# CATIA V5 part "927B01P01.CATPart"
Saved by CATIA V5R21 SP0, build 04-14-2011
Part number: 927B01P01
Bounding box of the stored display mesh (mm): x -17.1 to 17.1, y -76.2 to 76.2, z -4.4 to 4.4
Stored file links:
  C:\Users\ALI OZGUN\Desktop\alhan\927B01P01.CATPart
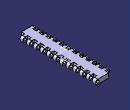
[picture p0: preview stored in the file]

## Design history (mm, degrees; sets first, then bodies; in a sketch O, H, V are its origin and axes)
Body1 (main body)
  Sketch1 on zx-plane, origin (0, 0, 0), H (-1, 0, 0), V (0, 0, 1)
    construction line L1 (-12.7, 0) -> (12.7, 0)
    point P1 (-12.7, 0)
    line L2 (-12.7, 4.4) -> (12.7, 4.4)
    line L3 (12.7, -4.4) -> (-12.7, -4.4)
    arc A1 centre (12.7, 0) radius 4.4 from (12.7, 4.4) to (12.7, -4.4) cw
    arc A2 centre (-12.7, 0) radius 4.4 from (-12.7, -4.4) to (-12.7, 4.4) cw
    distance L1 L2 = 4.4
    length L1 = 25.4
    distance P1 V = 12.7
    coincidence: P1 H
    horizontal: L1 H
    tangency: A1 L2, A2 L2, A1 L3, A2 L3
  Pad1: profile Sketch1, direction (0, 1, 0), length 76.2, mirrored extent
  Sketch2 on face of Pad1 from Sketch1.L2, origin (0, 0, 4.4), H (1, 0, 0), V (0, 1, 0)
    line L1 (-22.3127, -63.5) -> (-9.75, -63.5)
    line L2 (-9.75, -63.5) -> (-9.75, -70.6)
    line L3 (-9.75, -70.6) -> (-22.3127, -70.6)
    line L4 (-22.3127, -70.6) -> (-22.3127, -63.5)
    line L5 (24.6678, -76.95) -> (9.75, -76.95)
    line L6 (9.75, -76.95) -> (9.75, -69.85)
    line L7 (9.75, -69.85) -> (24.6678, -69.85)
    line L8 (24.6678, -69.85) -> (24.6678, -76.95)
    reference projected line E1 (-12.7, -76.2) -> (12.7, -76.2) from edge [start face of Pad1 | face of Pad1 from Sketch1.L2]
    reference projected line E2 (-12.7, -76.2) -> (12.7, -76.2) from edge [start face of Pad1 | face of Pad1 from Sketch1.L2]
    distance L3 E1 = 5.6
    length L4 = 7.1
    distance L7 L5 = 7.1
    distance L5 E2 = 0.75
    distance L2 L6 = 19.5
    distance L2 V = 9.75
    horizontal: L1 H, L3 H, L5 H, L7 H
    vertical: L2 V, L4 V, L6 V, L8 V
  Pocket1: profile Sketch2, direction (0, 0, -1), length 76.2
  RectPattern1: of Pocket1, direction 1 instances 12, spacing 12.7, along axis of face of Pad1 from Sketch1.A2
  Sketch3 on face of Pad1 from Sketch1.L3, origin (0, 0, -4.4), H (1, 0, 0), V (0, -1, 0)
    line L1 (-6.5, -54.6) -> (6.5, -54.6)
    line L2 (6.5, -54.6) -> (6.5, -73.7)
    line L3 (6.5, -73.7) -> (-6.5, -73.7)
    line L4 (-6.5, -73.7) -> (-6.5, -54.6)
    construction line L5 (-4.5, -51.1) -> (4.5, -51.1)
    point P5 (-4.5, -51.1)
    line L6 (-4.5, -49.6) -> (4.5, -49.6)
    line L7 (4.5, -52.6) -> (-4.5, -52.6)
    arc A1 centre (4.5, -51.1) radius 1.5 from (4.5, -49.6) to (4.5, -52.6) cw
    arc A2 centre (-4.5, -51.1) radius 1.5 from (-4.5, -52.6) to (-4.5, -49.6) cw
    reference projected line E1 (12.7, -76.2) -> (-12.7, -76.2) from edge [face of Pad1 from Sketch1.L3 | end face of Pad1]
    distance L5 L6 = 1.5
    distance L1 L3 = 19.1
    distance L4 L2 = 13
    distance L4 V = 6.5
    distance E1 L3 = 2.5
    distance P5 V = 4.5
    length L5 = 9
    distance L7 L1 = 2
    horizontal: L1 H, L3 H, L5 H
    vertical: L2 V, L4 V
    tangency: A1 L6, A2 L6, A1 L7, A2 L7
  Pocket2: profile Sketch3, direction (0, 0, 1), length 6
  RectPattern2: of Pocket2, direction 1 instances 6, spacing 25.8, along axis of face of Pad1 from Sketch1.A2 reversed
  Sketch4 on zx-plane, origin (0, 0, 0), H (-1, 0, 0), V (0, 0, 1)
    circle A1 centre (12.7, 0) radius 2.3
    point P1 (12.7, 0)
    circle A2 centre (-12.7, 0) radius 2.3
    point P2 (-12.7, 0)
    reference projected arc E1 centre (12.7, 0) radius 4.4 from (12.7, -4.4) to (12.7, 4.4) ccw from edge [face of RectPattern1 | face of Pad1 from Sketch1.A1]
    reference projected arc E2 centre (-12.7, 0) radius 4.4 from (-12.7, 4.4) to (-12.7, -4.4) ccw from edge [face of Pad1 from Sketch1.A2 | end face of Pad1]
    radius A1 = 2.3
    radius A2 = 2.3
    coincidence: P1 H, P2 H
    concentricity: P1 E1, A2 E2
  Pocket3: profile Sketch4, direction (0, -1, 0), length 97.8, mirrored extent
  Body2
    Solid1: linked copy from another document
    Symmetry1: ToTransfor Solid1, Reference yz-plane
    Translate1: Direction edge [face of Pocket1 from Sketch2.L2 | face of Pad1 from Sketch1.L3], ToTransfor Symmetry1, Length 6.35
    Body3
      Sketch5 on face of RectPattern1, origin (9.75, 0, 0), H (0, 1, 0), V (0, 0, 1)
      Pad2: profile Sketch5, direction (1, 0, 0), length 12
      Sketch6 on face of Pad2, origin (0, 69.85, 0), H (-1, 0, 0), V (0, 0, 1)
        point P2 (-21.75, 4.4)
        arc A1 centre (-16.4898, 1.5645) radius 9 from (-9.75, -4.4) to (-7.9481, 4.4) ccw
        point P8 (-21.75, 4.4)
        construction line L1 (-9.75, 4.4) -> (-21.75, 4.4)
        line L2 (-7.9481, 4.4) -> (-21.75, 4.4)
        line L3 (-9.75, -4.4) -> (-21.75, -4.4)
        line L4 (-21.75, -4.4) -> (-21.75, 4.4)
        radius A1 = 9
        coincidence: P2 P8
      Pad3: profile Sketch6, direction (0, 1, 0), up to face of Pad2
      RectPattern3: of the body so far, direction 1 instances 12, spacing 12.7, along edge [face of Pad3 | face of Pad3] reversed
    Add1: tool Body3
  Remove1: tool Body2
Body4
  Solid2: linked copy from another document
  Translate2: Direction yz-plane, Length 25.4, ToTransfor Solid2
